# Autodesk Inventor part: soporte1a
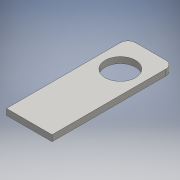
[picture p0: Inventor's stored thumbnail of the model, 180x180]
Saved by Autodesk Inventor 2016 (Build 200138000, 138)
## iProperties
Created: 2016-06
Part Number: soporte1a
Material: Genérico
Document SubType Name: Modeling
Designer: adm
Density: 1 g/cm^3
Appearance: Valor por defecto
Author: adm
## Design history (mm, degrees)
sketch "Boceto1"
  geometry: L1 (-15, -40)-(15, -40); L2 (15, -40)-(15, 40); L3 (15, 40)-(-15, 40); L4 (-15, 40)-(-15, -40); L5 (-15, -40)-(15, 40); L6 (15, -40)-(-15, 40); 1 further point
  constraints: 12 end point, 2 midpoint, 2 parallel, 1 horizontal, 1 perpendicular
  dimensions: "d0" = 30 distance of L3.end L2.end; "d1" = 80 distance of L2.end L1.end
extrude "Extrusión1" new body sketch "Boceto1" distance "d2" = 4; taper "d3" = 0 deg
fillet "Empalme1" dims "d4" = 5
sketch "Boceto2"
  geometry: L1 (10, 40)-(-10, 40) reference; C1 r 10 at (0, 20); 2 further points
  constraints: 1 centre point, 1 coincident
  dimensions: "d5" = 20 distance from line of point (0, 20) L1; "d6" = 20 diameter of C1
extrude "Extrusión2" cut sketch "Boceto2" distance "d7" = 4; taper "d8" = 0 deg
node "Sólido1"
